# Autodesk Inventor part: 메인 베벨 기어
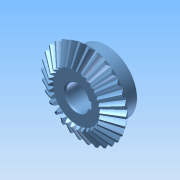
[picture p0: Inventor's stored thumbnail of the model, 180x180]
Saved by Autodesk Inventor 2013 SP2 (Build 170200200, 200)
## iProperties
Created: 2026-07
Part Number: 메인 베벨 기어
Material: Generic
Document SubType Name: Modeling
Designer: aa
Density: 1 g/cm^3
Author: aa
변환 표준: STEP AP214IS
전처리기: Build: 200, Release: 2013 SP2 Update 6 - Date: Thu 07/17/2014
전송 단위: 밀리미터
불확실성: 0.01
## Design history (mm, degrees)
node "메인 베벨기어1"
body "Solid1"
node "기준1"
